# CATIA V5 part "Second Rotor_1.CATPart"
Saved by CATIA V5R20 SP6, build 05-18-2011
Part number: Second Rotor
Bounding box of the stored display mesh (mm): x -42.215 to 36.484, y 35 to 43.5, z 116.834 to 197.162
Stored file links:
  E:\#01 CATIA Lecture Materials\#06 DMU\#04 DMU Page01 KIN EX04\Second Rotor_1.CATPart
  E:\#01 CATIA Lecture Materials\#06 DMU\#10 Kinematics Joints\#05 Gear Joint\Skeleton.CATPart
  E:\#01 CATIA Lecture Materials\#06 DMU\#04 DMU Page01 KIN EX04\DMU Page KIN EX04.CATProduct
  E:\#01 CATIA Lecture Materials\#06 DMU\#04 DMU Page01 KIN EX04\Main Body_1.CATPart
  E:\#01 CATIA Lecture Materials\#06 DMU\#10 Kinematics Joints\#002 Gear Joint(Rotor)\Third Rotor.CATPart
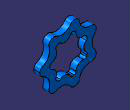
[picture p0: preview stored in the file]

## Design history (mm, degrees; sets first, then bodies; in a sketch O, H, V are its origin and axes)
Set1 "Rotor Axis Body"
  Line1 "Second Rotor Axis": stored without definition
  Extract1: ExtractElem face of Solid1
  Boundary1 "Outer Boundary.1": Boundary edge of Extract1
  Boundary2 "Inner Boundary.1": Boundary edge of Extract1
Body1 (main body)
Body2 "Second Rotor"
  Solid1: solid without history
